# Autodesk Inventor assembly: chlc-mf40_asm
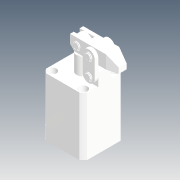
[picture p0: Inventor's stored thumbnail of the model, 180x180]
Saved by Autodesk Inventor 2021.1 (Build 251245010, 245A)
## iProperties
Company: Microsoft
Created: 2019-11
Part Number: chlc-mf40_asm
Description: STEP AP214
Document SubType Name: Assembly
Designer: user
Title: chlc-mf40_asm.STEP
Author: Windows
Revision Number: ÈÎºÎ
Sending System: SolidWorks 2015
Preprocessor: SwSTEP 2.0
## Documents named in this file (13)
- D:\Vault_2016\Projekty\Clamptek\Hydraulic\CHLC\CHLC-40\Inventor\CHLC-MF40\chlc-mf40_asm.iam
- D:\Vault_2016\Projekty\Clamptek\Hydraulic\CHLC\CHLC-40\Inventor\CHLC-MF40\CHLC-MF40-01.ipt
- D:\Vault_2016\Projekty\Clamptek\Hydraulic\CHLC\CHLC-40\Inventor\CHLC-MF40\CHLC-MF40-02.ipt
- D:\Vault_2016\Projekty\Clamptek\Hydraulic\CHLC\CHLC-40\Inventor\CHLC-MF40\CHLC-40-08.ipt
- D:\Vault_2016\Projekty\Clamptek\Hydraulic\CHLC\CHLC-40\Inventor\CHLC-MF40\CHLC-40-01.ipt
- D:\Vault_2016\Projekty\Clamptek\Hydraulic\CHLC\CHLC-40\Inventor\CHLC-MF40\CHLC-40-03.ipt
- D:\Vault_2016\Projekty\Clamptek\Hydraulic\CHLC\CHLC-40\Inventor\CHLC-MF40\CHLC-40-02.ipt
- D:\Vault_2016\Projekty\Clamptek\Hydraulic\CHLC\CHLC-40\Inventor\CHLC-MF40\CHLC-40-04.ipt
- D:\Vault_2016\Projekty\Clamptek\Hydraulic\CHLC\CHLC-40\Inventor\CHLC-MF40\TXF_ASM.iam
- D:\Vault_2016\Projekty\Clamptek\Hydraulic\CHLC\CHLC-40\Inventor\CHLC-MF40\M6.ipt
- D:\Vault_2016\Projekty\Clamptek\Hydraulic\CHLC\CHLC-40\Inventor\CHLC-MF40\CHLC-40-06.ipt
- D:\Vault_2016\Projekty\Clamptek\Hydraulic\CHLC\CHLC-40\Inventor\CHLC-MF40\M6LS.ipt
- D:\Vault_2016\Projekty\Clamptek\Hydraulic\CHLC\CHLC-40\Inventor\CHLC-MF40\M6LC.ipt
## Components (20 placed, 20 different names)
1. CHLC-MF40-01_1
2. CHLC-MF40-02_2
3. CHLC-40-08_3
4. CHLC-40-01_4
5. CHLC-40-03_5
6. CHLC-40-03_6
7. CHLC-40-02_7
8. CHLC-40-02_8
9. CHLC-40-04_9
10. TXF_ASM_10 [sub-assembly]
11. M6_11
12. CHLC-40-06_12
13. CHLC-40-06_13
14. CHLC-40-06_14
15. CHLC-40-06_15
16. CHLC-40-06_16
17. CHLC-40-06_17
18. M6LS_18
19. M6LC_19
20. M6LC_20
